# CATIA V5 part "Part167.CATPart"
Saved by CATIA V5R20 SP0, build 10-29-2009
Part number: FA 126700-2 comprimido
Revision: ANY
Definition: UNKNOWN
Nomenclature: FA 126700-2 comprimido
Source: Unknown
Bounding box of the stored display mesh (mm): x -2.8 to 2.8, y 0 to 5, z -2.8 to 2.8
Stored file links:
  C:\Users\Utente\Desktop\IO LAVORO\3D X SITO CF\CUMSA\3D files FA\FA 126700\Part167.CATPart
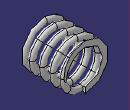
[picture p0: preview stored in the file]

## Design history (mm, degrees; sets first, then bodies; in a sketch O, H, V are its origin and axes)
Body1 "Cortar-Extruir1" (main body)
  Solid1: solid without history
